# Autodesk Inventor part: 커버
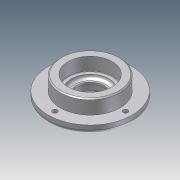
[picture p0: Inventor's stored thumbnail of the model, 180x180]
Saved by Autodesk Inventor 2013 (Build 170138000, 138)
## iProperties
Company: 한국ATC센터
Created: 2014-10
Part Number: 커버
Document SubType Name: Modeling
Designer: KYOUNG IL JANG
Density: 1 g/cm^3
Mass: 44.7286 g
Surface Area: 161.165 cm^2
Volume: 44.7286 cm^3
Material: 일반
Author: KYOUNG IL JANG
Revision Number: 1
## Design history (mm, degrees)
sketch "스케치1"
  geometry: C1 r 38 at (0, 0); 1 further point
  constraints: 1 centre point, 1 coincident
  dimensions: "d0" = 76 diameter of C1
extrude "돌출1" new body sketch "스케치1" distance "d1" = 7; taper "d2" = 0 deg
sketch "스케치2"
  geometry: C1 r 27 at (0, 0); 1 further point
  constraints: 1 centre point, 1 coincident
  dimensions: "d3" = 54 diameter of C1
extrude "돌출2" join sketch "스케치2" distance "d4" = 13; taper "d5" = 0 deg
sketch "스케치3"
  geometry: C1 r 20 at (0, 0); 1 further point
  constraints: 1 centre point, 1 coincident
  dimensions: "d6" = 40 diameter of C1
extrude "돌출3" join sketch "스케치3" distance "d7" = 5; taper "d8" = 0 deg
hole "구멍1" diameter "d11" = 25; stored, may be unused: countersink angle "d15" = 90 deg, drill point angle "d17" = 118 deg; dims "d9" = 10, "d10" = 10, "d12" = 6, "d13" = 32, "d14" = 8.3, "d16" = 8
hole "구멍2" diameter "d20" = 34; stored, may be unused: countersink angle "d24" = 90 deg, drill point angle "d26" = 0 deg; dims "d18" = 10, "d19" = 10, "d21" = 6, "d22" = 40, "d23" = 12, "d25" = 3
fillet "모깎기2" dims "d34" = 3
fillet "모깎기1" dims "d27" = 0.3
chamfer "모따기1" distance "d28" = 1; stored, may be unused: second distance "d29" = 2, angle "d30" = 45 deg
chamfer "모따기2" distance "d31" = 1.2; stored, may be unused: second distance "d32" = 2, angle "d33" = 30 deg
sketch "스케치4" dims "d35" = 64
  geometry: 3 further points
  constraints: 2 horizontal alignment, 1 coincident, 2 other
hole "구멍3" sketch "스케치4" at (32, 0) diameter "d36" = 4.5; stored, may be unused: countersink angle "d40" = 90 deg, drill point angle "d42" = 118 deg; dims "d37" = 6, "d38" = 8, "d39" = 4.4, "d41" = 13
node "솔리드1"
pattern_circular "원형 패턴1" dims angle "d44" = 360 deg
